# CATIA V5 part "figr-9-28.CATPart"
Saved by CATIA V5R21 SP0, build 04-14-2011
Part number: Part1
Bounding box of the stored display mesh (mm): x -75 to 75, y -50 to 50, z 0 to 40
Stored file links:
  D:\CATIA V5R21 E-RESOURCES\CATIA-V5R21\catia-v5r21-prt\c09-catia-v5r20-prt\c09-catia-v5r21-figr-9-28.CATPart
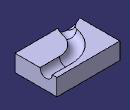
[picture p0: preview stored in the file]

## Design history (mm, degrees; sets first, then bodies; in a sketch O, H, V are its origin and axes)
Body1 (main body)
  Sketch1 on xy-plane, origin (0, 0, 0), H (1, 0, 0), V (0, 1, 0)
    line L1 (-75, 50) -> (75, 50)
    line L2 (75, 50) -> (75, -50)
    line L3 (75, -50) -> (-75, -50)
    line L4 (-75, -50) -> (-75, 50)
    axis line L5 (75, -50) -> (-75, 50)
    length L2 = 100
    length L3 = 150
    horizontal: L1 H, L3 H
    vertical: L2 V, L4 V
    midpoint: O L5
  Pad1: profile Sketch1, direction (0, 0, 1), length 40
  Sketch2 on face of Pad1, origin (75, 0, 0), H (0, 1, 0), V (0, 0, 1)
    arc A1 centre (24.1478, 40) radius 14.6047 from (9.543, 40) to (38.7525, 40) ccw
    point P1 (24.1478, 40)
    reference projected point E1 (24.1478, 40) from vertex of Sketch3
    line L1 (9.543, 40) -> (38.7525, 40)
    coincidence: P1 E1
    horizontal: L1 H
  Sketch3 on face of Pad1, origin (0, 0, 40), H (1, 0, 0), V (0, 1, 0)
    point P1 (75, 24.1478)
    line L1 (75, 24.1478) -> (28.6577, 24.1478)
    arc A1 centre (28.6577, -39.2062) radius 63.354 from (28.6577, 24.1478) to (-33.8383, -28.8149) ccw
    arc A2 centre (-62.192, -24.1005) radius 28.7429 from (-33.8383, -28.8149) to (-49.7271, -50) cw
    point P6 (-49.7271, -50)
    reference projected line E1 (75, -50) -> (75, 50) from edge [face of Pad1 | face of Pad1]
    reference projected line E2 (-75, -50) -> (75, -50) from edge [face of Pad1 | face of Pad1]
    horizontal: L1 H
    tangency: A1 L1, A2 A1
    coincidence: P1 E1, P6 E2
  Slot1: profile Sketch2, centre curve Sketch3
